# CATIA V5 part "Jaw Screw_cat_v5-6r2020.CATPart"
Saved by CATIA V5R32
Part number: Jaw Screw
Bounding box of the stored display mesh (mm): x -9 to 9, y 0 to 138, z -8.948 to 9
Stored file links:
  D:\PROJECTS\Project 2022\CATIA V5 6R 2022\Resources\Tutorial Files\c13_catia_v5_6r2022_tut\c13tut2\Bench vice\Jaw Screw_cat_v5-6r2020.CATPart
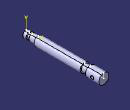
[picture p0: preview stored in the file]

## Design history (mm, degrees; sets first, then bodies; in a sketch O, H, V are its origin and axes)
Body1 (main body)
  Sketch1 on yz-plane, origin (0, 0, 0), H (0, 1, 0), V (0, 0, 1)
    line L1 (0, 0) -> (0, 6)
    line L2 (0, 6) -> (6, 6)
    line L3 (6, 6) -> (6, 4)
    line L4 (6, 4) -> (11, 4)
    line L5 (11, 4) -> (11, 6)
    point P5 (11, 6)
    line L6 (11, 6) -> (22, 6)
    line L7 (22, 6) -> (22, 8)
    line L8 (22, 8) -> (104, 8)
    line L9 (104, 8) -> (104, 6)
    point P9 (104, 6)
    line L10 (104, 6) -> (114, 6)
    line L11 (114, 6) -> (114, 9)
    line L12 (114, 9) -> (138, 9)
    line L13 (138, 9) -> (138, 0)
    point P13 (138, 0)
    line L14 (138, 0) -> (0, 0)
    distance L2 L14 = 6
    distance L8 L14 = 8
    distance L12 L14 = 9
    length L2 = 6
    length L4 = 5
    length L8 = 82
    length L10 = 10
    length L12 = 24
    length L14 = 138
    distance L4 L14 = 4
    vertical: L1 V, L3 V, L5 V, L7 V, L9 V, L11 V, L13 V
    horizontal: L2 H, L4 H, L6 H, L8 H, L10 H, L12 H, L14 H
    coincidence: P5 L2, P9 L6, P13 H
  Shaft1: profile Sketch1, axis edge of Sketch1, angle 360
  Sketch2 on yz-plane, origin (0, 0, 0), H (0, 1, 0), V (0, 0, 1)
    circle A1 centre (126, 0) radius 3
    point P1 (126, 0)
    radius A1 = 3
    distance P1 V = 126
    coincidence: P1 H
  Pocket1: profile Sketch2, direction (-1, 0, 0), length 20, mirrored extent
